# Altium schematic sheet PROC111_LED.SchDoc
size 431 x 279 mm; Date: Not shown in title block; ApprovedBy: Not shown in title block; CheckedBy: Not shown in title block; Author: Not shown in title block; CompanyName: Not shown in title block; Engineer: Not shown in title block; Organization: Not shown in title block; Address1: Not shown in title block; Address2: Not shown in title block; Address3: Not shown in title block; Address4: Not shown in title block; DocumentNumber: 23; Revision: Use project parameter SCH_Rev; SheetNumber: 23; SheetTotal: 24; PageSetup: Record=PageOptions¦CenterHorizontal=True¦CenterVertical=True¦PrintScale=1.00¦XCorrection=1.00¦YCorrection=1.00¦PrintKind=0¦BorderSize=5000000¦LeftOffset=0¦BottomOffset=0¦Orientation=2¦PaperLength=1000¦PaperWidth=1000¦Scale=100¦PaperSource=15¦PrintQuality=600¦MediaType=1¦DitherType=10¦PaperKind=Letter¦PrintScaleMode=1
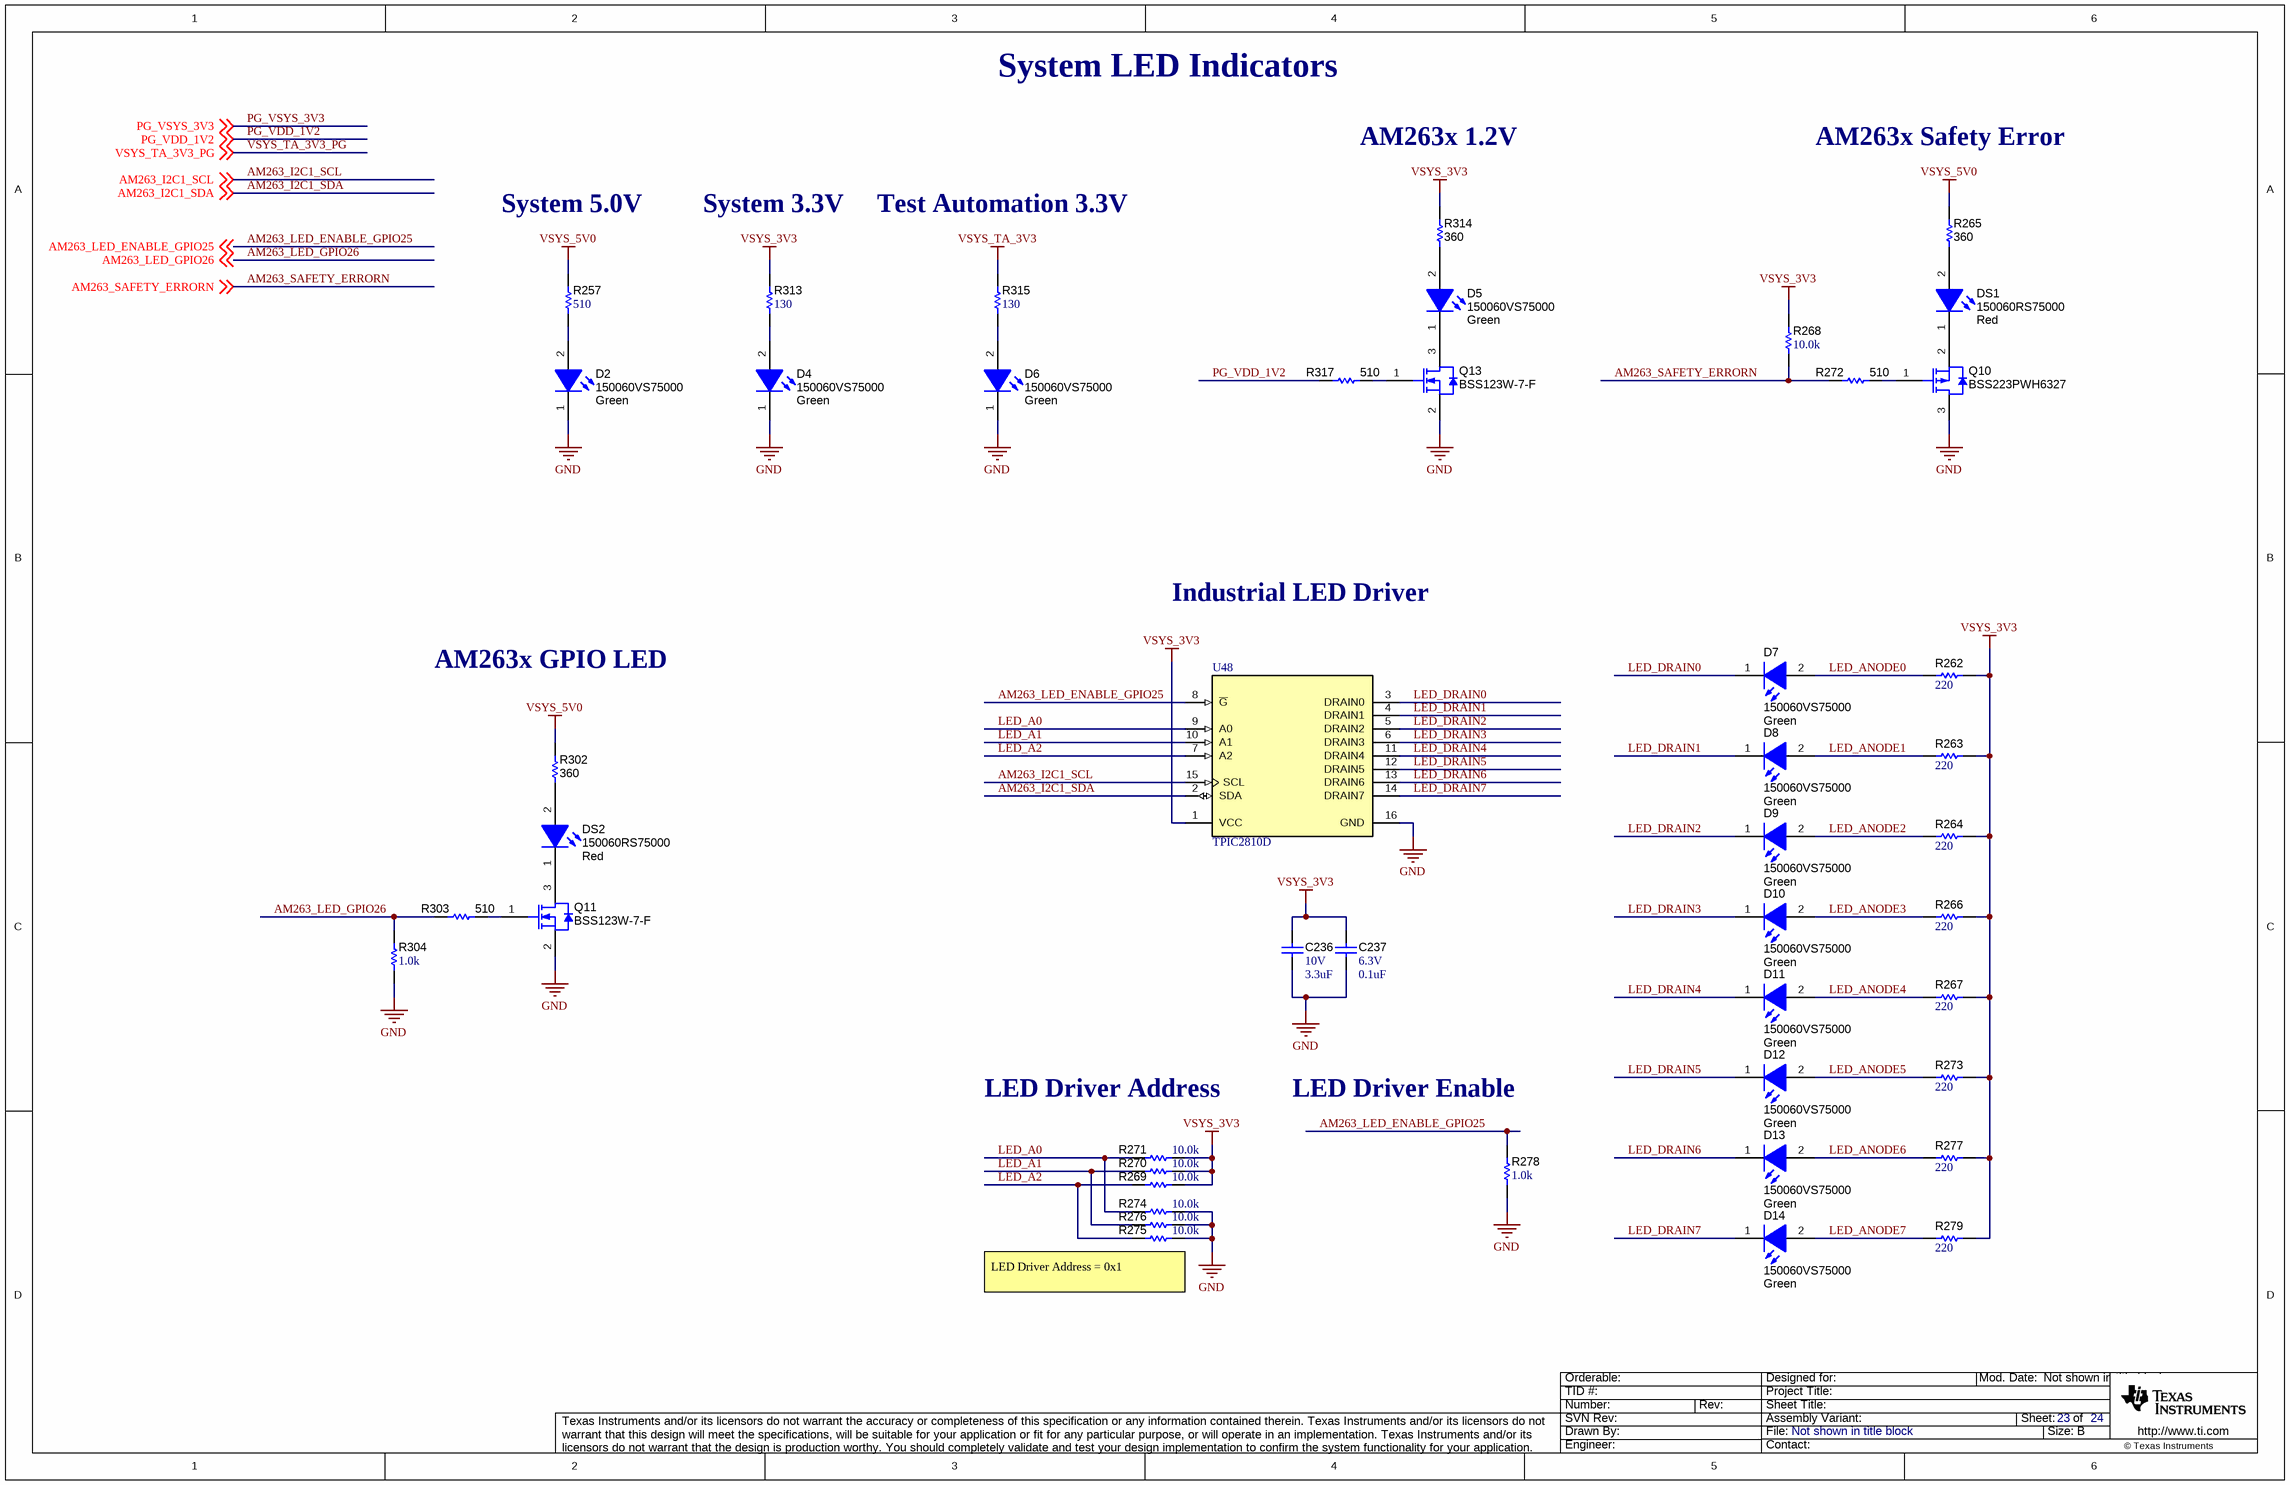
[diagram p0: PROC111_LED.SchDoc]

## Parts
C236  VDC_V: 10V  ValueDisplayed: 3.3uF  [0603]  (hidden comment: C1608X7S1A335K080AC)
C237  VDC_V: 6.3V  ValueDisplayed: 0.1uF  [0402]  (hidden comment: GRM155R70J104KA01D)
D2  150060VS75000  value Green  [WL-SMCW_GREEN]
D4  150060VS75000  value Green  [WL-SMCW_GREEN]
D5  150060VS75000  value Green  [WL-SMCW_GREEN]
D6  150060VS75000  value Green  [WL-SMCW_GREEN]
D7  150060VS75000  value Green  [WL-SMCW_GREEN]
D8  150060VS75000  value Green  [WL-SMCW_GREEN]
D9  150060VS75000  value Green  [WL-SMCW_GREEN]
D10  150060VS75000  value Green  [WL-SMCW_GREEN]
D11  150060VS75000  value Green  [WL-SMCW_GREEN]
D12  150060VS75000  value Green  [WL-SMCW_GREEN]
D13  150060VS75000  value Green  [WL-SMCW_GREEN]
D14  150060VS75000  value Green  [WL-SMCW_GREEN]
DS1  150060RS75000  value Red  [WL-SMCW_RED]
DS2  150060RS75000  value Red  [WL-SMCW_RED]
Q10  BSS223PWH6327  [SOT-323]
Q11  BSS123W-7-F  [SOT-323]
Q13  BSS123W-7-F  [SOT-323]
R257  ValueDisplayed: 510  [0402]  (hidden comment: ERJ-2RKF5100X)
R262  ValueDisplayed: 220  [0402]  (hidden comment: ERJ-2RKF2200X)
R263  ValueDisplayed: 220  [0402]  (hidden comment: ERJ-2RKF2200X)
R264  ValueDisplayed: 220  [0402]  (hidden comment: ERJ-2RKF2200X)
R265  ValueDisplayed: 360  [0402L]  (hidden comment: ERJ-2GEJ361X)
R266  ValueDisplayed: 220  [0402]  (hidden comment: ERJ-2RKF2200X)
R267  ValueDisplayed: 220  [0402]  (hidden comment: ERJ-2RKF2200X)
R268  ValueDisplayed: 10.0k  [0402]  (hidden comment: ERJ-2RKF1002X)
R269  ValueDisplayed: 10.0k  [0402]  (hidden comment: ERJ-2RKF1002X)
R270  ValueDisplayed: 10.0k  [0402]  (hidden comment: ERJ-2RKF1002X)
R271  ValueDisplayed: 10.0k  [0402]  (hidden comment: ERJ-2RKF1002X)
R272  ValueDisplayed: 510  [0402L]  (hidden comment: ERJ-2GEJ511X)
R273  ValueDisplayed: 220  [0402]  (hidden comment: ERJ-2RKF2200X)
R274  ValueDisplayed: 10.0k  [0402]  (hidden comment: ERJ-2RKF1002X)
R275  ValueDisplayed: 10.0k  [0402]  (hidden comment: ERJ-2RKF1002X)
R276  ValueDisplayed: 10.0k  [0402]  (hidden comment: ERJ-2RKF1002X)
R277  ValueDisplayed: 220  [0402]  (hidden comment: ERJ-2RKF2200X)
R278  ValueDisplayed: 1.0k  [0402]  (hidden comment: ERJ-2GEJ102X)
R279  ValueDisplayed: 220  [0402]  (hidden comment: ERJ-2RKF2200X)
R302  ValueDisplayed: 360  [0402L]  (hidden comment: ERJ-2GEJ361X)
R303  ValueDisplayed: 510  [0402L]  (hidden comment: ERJ-2GEJ511X)
R304  ValueDisplayed: 1.0k  [0402]  (hidden comment: ERJ-2GEJ102X)
R313  ValueDisplayed: 130  [0402]  (hidden comment: CRCW0402130RFKED)
R314  ValueDisplayed: 360  [0402L]  (hidden comment: ERJ-2GEJ361X)
R315  ValueDisplayed: 130  [0402]  (hidden comment: CRCW0402130RFKED)
R317  ValueDisplayed: 510  [0402L]  (hidden comment: ERJ-2GEJ511X)
U48  TPIC2810D  [D0016A_N]

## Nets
GND: C236.2 C237.2 D2.1(K) D4.1(K) D6.1(K) Q10.3(D) Q11.2(S) Q13.2(S) R274.1 R275.1 R276.1 R278.1 R304.1 U48.16(GND)
VSYS_3V3: C236.1 C237.1 R262.2 R263.2 R264.2 R266.2 R267.2 R268.2 R269.1 R270.1 R271.1 R273.2 R277.2 R279.2 R313.2 R314.2 U48.1(VCC)
VSYS_5V0: R257.2 R265.2 R302.2
VSYS_TA_3V3: R315.2
AM263_I2C1_SCL: U48.15(SCL) ; off-sheet AM263_I2C1_SCL
AM263_I2C1_SDA: U48.2(SDA) ; off-sheet AM263_I2C1_SDA
AM263_LED_ENABLE_GPIO25: R278.2 U48.8(~{G}) ; off-sheet AM263_LED_ENABLE_GPIO25
AM263_LED_GPIO26: R303.1 R304.2 ; off-sheet AM263_LED_GPIO26
AM263_SAFETY_ERRORN: R268.1 R272.1 ; off-sheet AM263_SAFETY_ERRORN
LED_A0: R271.2 R274.2 U48.9(A0)
LED_A1: R270.2 R276.2 U48.10(A1)
LED_A2: R269.2 R275.2 U48.7(A2)
LED_ANODE0: D7.2(A) R262.1
LED_ANODE1: D8.2(A) R263.1
LED_ANODE2: D9.2(A) R264.1
LED_ANODE3: D10.2(A) R266.1
LED_ANODE4: D11.2(A) R267.1
LED_ANODE5: D12.2(A) R273.1
LED_ANODE6: D13.2(A) R277.1
LED_ANODE7: D14.2(A) R279.1
LED_DRAIN0: D7.1(K) U48.3(DRAIN0)
LED_DRAIN1: D8.1(K) U48.4(DRAIN1)
LED_DRAIN2: D9.1(K) U48.5(DRAIN2)
LED_DRAIN3: D10.1(K) U48.6(DRAIN3)
LED_DRAIN4: D11.1(K) U48.11(DRAIN4)
LED_DRAIN5: D12.1(K) U48.12(DRAIN5)
LED_DRAIN6: D13.1(K) U48.13(DRAIN6)
LED_DRAIN7: D14.1(K) U48.14(DRAIN7)
PG_VDD_1V2: R317.1 ; off-sheet PG_VDD_1V2
NetD2_2: D2.2(A) R257.1
NetD4_2: D4.2(A) R313.1
NetD5_1: D5.1(K) Q13.3(D)
NetD5_2: D5.2(A) R314.1
NetD6_2: D6.2(A) R315.1
NetDS1_1: DS1.1(K) Q10.2(S)
NetDS1_2: DS1.2(A) R265.1
NetDS2_1: DS2.1(K) Q11.3(D)
NetDS2_2: DS2.2(A) R302.1
NetQ10_1: Q10.1(G) R272.2
NetQ11_1: Q11.1(G) R303.2
NetQ13_1: Q13.1(G) R317.2

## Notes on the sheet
- System LED Indicators
- AM263x 1.2V
- AM263x Safety Error
- System 5.0V
- System 3.3V
- Test Automation 3.3V
- Industrial LED Driver
- AM263x GPIO LED
- LED Driver Address
- LED Driver Enable
- (near R275) LED Driver Address = 0x1

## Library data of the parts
C236 = CMP-0007057-4: CAP, CERM, 3.3 uF, 10 V, +/- 10%, X7S, 0603; Manufacturer: TDK; TaMin_C: -55°C; ESR_ohm: 4.796m; Polarized: N; SizeAreaWB_mm2: 4.68; Value1: 0.004796 ohm; U/M: EA; Value: 3.3uF; TaMax_C: 125°C; SizeZ_mm: 1; SizeX_mm: 1.6; SizeY_mm: 0.8; SizeArea_mm2: 1.28; Cap_F: 3.3µF; IRMS_A: 2.3752A; AEC Category: Q200
C237 = CMP-0006623-2: CAP, CERM, 0.1 uF, 6.3 V, +/- 10%, X7R, 0402; Manufacturer: MuRata; TaMin_C: -55°C; Polarized: N; SizeAreaWB_mm2: 3; Value1: Unknown; U/M: EA; Value: 0.1uF; TaMax_C: 125°C; SizeZ_mm: 0.6; SizeX_mm: 1; SizeY_mm: 0.5; Cap_F: 100nF; AEC Category: Q200
D2 D4-D14 = CMP-0002894-2: LED, Green, SMD; Manufacturer: Wurth Elektronik; Io_A: 20mA; Value1: W; Vf_V: 2V; Type: AlInGaP
DS1 DS2 = CMP-0002947-3: LED, Red, SMD; Manufacturer: Wurth Elektronik; Value1: 0.072W; Vf_V: 2V; Angle: 140; Tjmax_C: 85°C; Type: AlInGaP; Vr_V: 5V; Io_A: 30mA; Power_TotalModule: 72mW
Q10 = CMP-0000010-3: MOSFET, P-CH, -20 V, -0.39 A, SOT-323; Alternate Manufacturer: None; Manufacturer: Infineon Technologies; Value: -20V; Rdson45_ohm: 1.2; SizeX_mm: 2.2; AEC Category: Q101; ChMode: Enhancement; Vgs_V: -12V; Value1: 1; IdsMax_A: -390mA; ChType: P; SizeAreaWB_mm2: 10.24; QgTyp_nC: -0.5; SizeArea_mm2: 4.84; SizeZ_mm: 1.1
Q11 Q13 = CMP-0000948-2: MOSFET, N-CH, 100 V, 0.17 A, SOT-323; Alternate Manufacturer: None; Manufacturer: Diodes Inc.; SizeZ_mm: 1.1; ChType: N; Value1: 1; VdsMax_V: 100V; SizeX_mm: 2.2; Vgs_V: 20V; Value: 100V; Rdson45_ohm: 10; SizeArea_mm2: 4.84; AEC Category: Q101; IdsMax_A: 170mA; SizeAreaWB_mm2: 10.24; U/M: EA
R257 = CMP-0026704-1: RES, 510, 1%, 0.1 W, 0402; Manufacturer: Panasonic; Power_W: 100mW; TempCo: 100 ppm/C; Value_Code: 510R; U/M: EA; Value: 510; SizeX_mm: 1; SizeY_mm: 0.5; SizeZ_mm: 0.6; Value2: 0.1W; VDC_V: 50V; AEC Category: Q200
R262-R264 R266 R267 R273 R277 R279 = CMP-0026680-1: RES, 220, 1%, 0.1 W, AEC-Q200 Grade 0, 0402; Manufacturer: Panasonic; Power_W: 100mW; TempCo: 100 ppm/C; Value_Code: 220R; U/M: EA; Value: 220; SizeX_mm: 1; SizeY_mm: 0.5; SizeZ_mm: 0.6; Value2: 0.1W; AEC Qualified: Y; VDC_V: 50V; AEC Grade: 0; AEC Category: Q200
R265 R302 R314 = CMP-0078194-1: RES, 360, 5%, 0.1 W, AEC-Q200 Grade 0, 0402; Manufacturer: Panasonic; Value_Code: 360R; SizeArea_mm2: 0.5; AEC Qualified: Y; AEC Category: Q200; Value: 360; SizeZ_mm: 0.6; EIA_Code: E24; TempCo: 200 ppm/C; AEC Grade: 0; Power_W: 100mW; VDC_V: 50V; Value2: 0.1W; U/M: EA; SizeX_mm: 1
R268-R271 R274-R276 = CMP-0026658-1: RES, 10.0 k, 1%, 0.1 W, 0402; Manufacturer: Panasonic; Power_W: 100mW; TempCo: 100 ppm/C; Value_Code: 10k0; U/M: EA; Value: 10.0k; EIA_Code: E96; Res_ohm: 10k; SizeX_mm: 1; SizeY_mm: 0.5; SizeZ_mm: 0.6; Value2: 0.1W; VDC_V: 50V; AEC Category: Q200
R272 R303 R317 = CMP-0078212-1: RES, 510, 5%, 0.1 W, AEC-Q200 Grade 0, 0402; Manufacturer: Panasonic; Value_Code: 510R; SizeArea_mm2: 0.5; AEC Qualified: Y; AEC Category: Q200; Value: 510; SizeZ_mm: 0.6; EIA_Code: E24; TempCo: 200 ppm/C; AEC Grade: 0; Power_W: 100mW; VDC_V: 50V; Value2: 0.1W; U/M: EA; SizeX_mm: 1
R278 R304 = CMP-0078193-1: RES, 1.0 k, 5%, 0.1 W, AEC-Q200 Grade 0, 0402; Manufacturer: Panasonic; Value_Code: 1k00; SizeArea_mm2: 0.5; AEC Qualified: Y; AEC Category: Q200; Res_ohm: 1k; Value: 1.0k; SizeZ_mm: 0.6; Green_REACh: Passed; EIA_Code: E24; TempCo: 200 ppm/C; AEC Grade: 0; Power_W: 100mW; VDC_V: 50V; Value2: 0.1W; Green_Lifecycle: Active; U/M: EA; SizeX_mm: 1
R313 R315 = CMP-0025998-3: RES, 130, 1%, 0.063 W, AEC-Q200 Grade 0, 0402; Manufacturer: Vishay-Dale; Power_W: 63mW; TempCo: 100 ppm/C; Value_Code: 130R; Value: 130; EIA_Code: E96; SizeX_mm: 1; SizeY_mm: 0.5; SizeZ_mm: 0.6; Value2: 0.063W; AEC Qualified: Y; VDC_V: 50V; AEC Category: Q200; AEC Grade: 0
U48 = CMP-0044782-1: 8-Bit LED Driver with I2C Interface, D0016A, TUBE; Manufacturer: Texas Instruments; IO(PEAK)(A): 0.21; Priority (type 2): 1; rDS(on)(Ohms): 5; VDS(Max)(V): 40; IO(CONT)(A): 0.1; ICC(uA): 620; tPLH(ns): 1150; Rating: Catalog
